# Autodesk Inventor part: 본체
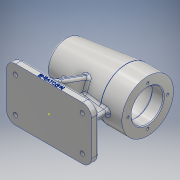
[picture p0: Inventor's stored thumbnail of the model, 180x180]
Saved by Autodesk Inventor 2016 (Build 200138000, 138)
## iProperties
Created: 2018-09
Part Number: 본체
Material: 알루미늄 6061
Document SubType Name: Modeling
Designer: CAMTIC
Density: 2.7 g/cm^3
Appearance: 알루미늄 - 평지
Mass: 734.322 g
Surface Area: 664.891 cm^2
Volume: 271.971 cm^3
Author: CAMTIC
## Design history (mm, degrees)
sketch "스케치1"
  geometry: L1 (56, -35)-(-56, -35); L2 (-56, -35)-(-56, 35); L3 (-56, 35)-(56, 35); L4 (56, 35)-(56, -35); L5 (0, -49)-(0, 49) reference; L6 (-78.4, 0)-(78.4, 0) reference; 1 further point
  constraints: 8 end point, 2 parallel, 1 horizontal, 1 perpendicular, 2 other
  dimensions: "d0" = 112 distance of L2.end L3.end; "d1" = 70 distance of L1.end L2.end
extrude "돌출1" new body sketch "스케치1" distance "d2" = 10; taper "d3" = 0 deg
sketch "스케치3"
  geometry: L1 (-56, 0)-(-56, 10) reference; L2 (-56, 10)-(56, 10) reference; L3 (56, 10)-(56, 0) reference; L4 (56, 0)-(-56, 0) reference; L5 (-78.4, 0)-(78.4, 0) reference; L6 (0, 12)-(0, -2) reference; L7 (-89.894, 74)-(120.731, 74); L8 (56, 74)-(56, 108); L9 (56, 108)-(28, 108); L10 (-56, 115.931)-(-56, 37.674); L11 (28, 108)-(-52.27, 98.144); L12 (-56, 74)-(56, 74); A1 r 80 centre (24, 74) between (54.397, 0) and (56, 0.679); A2 r 80 centre (24, 74) between (-52.27, 98.144) and (-56, 74); 1 further point
  constraints: 12 end point, 5 point on line, 4 point on circle, 2 centre point, 2 collinear, 2 horizontal, 2 vertical, 1 tangent
  dimensions: "d4" = 74 distance between parallel lines of L7 L4; "d5" = 34 distance of L8.start L8.end; "d6" = 28 distance of L8.end L9.end; "d7" = 112 distance between parallel lines of L8 L10; "d8" = 7 deg angle of L9 L11; "d10" = 80 radius of A2
revolve "회전1" sketch "스케치3" stored, may be unused: angle "d11" = 90 deg
sketch "스케치4"
  geometry: L1 (-56, 0)-(-56, 10) reference; L2 (-56, 10)-(56, 10) reference; L3 (56, 10)-(56, 0) reference; L4 (56, 0)-(-56, 0) reference; L5 (-52.27, 98.144)-(28, 108) reference; L6 (28, 108)-(56, 108) reference; L7 (56, 108)-(56, 40) reference; L8 (56, 40)-(28, 40) reference; L9 (28, 40)-(-52.27, 49.856) reference; L10 (-38, 10)-(-25.942, 55); L11 (-25.942, 55)-(38, 55); L12 (38, 55)-(38, 10); L13 (56, 10)-(-56, 10) reference; L14 (38, 10)-(-38, 10); A1 r 80 centre (24, 74) between (-52.27, 98.144) and (-52.27, 49.856) reference; 1 further point
  constraints: 8 end point, 2 point on line, 1 collinear, 1 horizontal, 1 perpendicular
  dimensions: "d12" = 18 distance from line of L1 L10.start; "d13" = 18 distance between parallel lines of L3 L12; "d14" = 105 deg angle of L2 L10; "d15" = 45 distance of L11.end L12.end
extrude "돌출2" join sketch "스케치4" stored distance "d16" = 8; taper "d17" = 0 deg
fillet "모깎기2" dims "d51" = 12
fillet "모깎기13" dims "d75" = 3
sketch "스케치5"
  geometry: L1 (7, -35)-(0, -35) reference; L2 (0, -35)-(0, 35) reference; L3 (0, 35)-(7, 35) reference; L4 (10, 32)-(10, 4) reference; L5 (10, 4)-(43.701, 4) reference; L6 (43.701, -4)-(10, -4) reference; L7 (10, -4)-(10, -32) reference; L8 (0, 49)-(0, -49) reference; L9 (-21.6, 0)-(129.6, 0) reference; L10 (10, -35)-(10, 35) reference; L11 (10, 35)-(10, -35); L12 (60, -15.902)-(60, 15.902); L13 (60, 15.902)-(8.026, 34.819); L14 (60, -15.902)-(8.026, -34.819); L15 (8.026, 34.819)-(8.026, -34.819); A1 r 30.562 centre (74, 0) between (43.701, -4) and (43.701, 4) reference; A2 r 3 centre (7, -32) between (7, -35) and (10, -32) reference; A3 r 3 centre (7, 32) between (10, 32) and (7, 35) reference; 1 further point
  constraints: 10 end point, 2 symmetric about line, 1 parallel, 1 point on circle, 1 point on line, 1 tangent, 1 vertical
  dimensions: "d19" = 50 distance between parallel lines of L7 L12; "d76" = 20 deg angle of L13 L3
extrude "돌출3" join sketch "스케치5" stored distance "d20" = 8; taper "d21" = 0 deg
sketch "스케치6"
  geometry: L1 (56, 7)-(56, 0) reference; L2 (56, 0)-(-56, 0) reference; L3 (-56, 0)-(-56, 7) reference; L4 (-53, 10)-(-38, 10) reference; L5 (-38, 10)-(-28.115, 46.89) reference; L6 (-28.115, 46.89)-(-52.27, 49.856) reference; L7 (-52.27, 98.144)-(28, 108) reference; L8 (28, 108)-(56, 108) reference; L9 (56, 108)-(56, 40) reference; L10 (56, 40)-(38, 40) reference; L11 (38, 40)-(38, 10) reference; L12 (38, 10)-(53, 10) reference; L13 (-78.4, 0)-(78.4, 0) reference; L14 (0, 129.6)-(0, -21.6) reference; L15 (56, 40)-(56, 108) reference; L16 (56, 95)-(41, 95); L17 (41, 95)-(41, 98); L18 (41, 98)-(-13, 98); L19 (-13, 98)-(-13, 95); L20 (-13, 95)-(-25, 95); L21 (-25, 95)-(-25, 91.5); L22 (-25, 91.5)-(-43, 91.5); L23 (-43, 91.5)-(-43, 90); L24 (-43, 90)-(-47, 90); L25 (-47, 90)-(-47, 84.5); L26 (-52.27, 49.856)-(-52.27, 98.144) reference; L27 (-47, 84.5)-(-50, 84.5); L28 (-50, 84.5)-(-50, 74); L29 (56, 74)-(-128.462, 74); L30 (-50, 74)-(56, 74); L31 (56, 95)-(56, 74); A1 r 80 centre (24, 74) between (-52.27, 98.144) and (-52.27, 49.856) reference; A2 r 3 centre (53, 7) between (56, 7) and (53, 10) reference; A3 r 3 centre (-53, 7) between (-53, 10) and (-56, 7) reference; 1 further point
  constraints: 30 end point, 12 perpendicular, 2 collinear, 2 point on line, 1 midpoint, 1 parallel
  dimensions: "d22" = 21 distance between parallel lines of L29 L16; "d23" = 15 distance of L16.start L16.end; "d24" = 54 distance of L17.end L18.end; "d25" = 24 distance between parallel lines of L29 L18; "d26" = 12 distance of L19.end L20.end; "d27" = 21 distance between parallel lines of L29 L20; "d28" = 18 distance of L21.end L22.end; "d29" = 17.5 distance between parallel lines of L29 L22; "d30" = 4 distance of L23.end L24.end; "d31" = 16 distance between parallel lines of L29 L24; "d32" = 10.5 distance between parallel lines of L29 L27; "d33" = 3 distance of L25.end L27.end
revolve "회전2" sketch "스케치6" stored, may be unused: angle "d34" = 90 deg
fillet "모깎기1" dims "d38" = 3, "d39" = 0.3
chamfer "모따기1" distance "d35" = 1; stored, may be unused: second distance "d36" = 2, angle "d37" = 45 deg
sketch "스케치7" dims "d40" = 52
  geometry: L1 (0, 0)-(0, 55.004); C1 r 10.5 at (0, 0) reference; 3 further points
  constraints: 2 end point, 1 coincident, 1 point on line, 1 vertical, 1 vertical alignment, 2 other
hole "구멍1" sketch "스케치7" at (0, 26) diameter "d41" = 3.242; stored, may be unused: countersink angle "d45" = 90 deg, drill point angle "d47" = 118 deg; dims "d42" = 8, "d43" = 4, "d44" = 2, "d46" = 11
hole "구멍2" diameter "d54" = 5.5; stored, may be unused: countersink angle "d58" = 90 deg, drill point angle "d60" = 118 deg; dims "d52" = 10, "d53" = 10, "d55" = 8, "d56" = 9.5, "d57" = 5.4, "d59" = 11
fillet "모깎기12" dims "d74" = 3
fillet "모깎기14" dims "d77" = 3
fillet "모깎기15" dims "d78" = 3
sketch "스케치9"
  geometry: L1 (88, 0)-(0, 0) reference; L2 (100, 0)-(100, 7) reference; 2 further points
  constraints: 1 other
  dimensions: "d84" = 3 distance from line of L1 point (44, 3); "d85" = 56 distance from line of L2 point (44, 3)
feature "엠보싱2" sketch "스케치9" dims "d0" = 112, "d1" = 70, "d86" = 0.5, "d87" = 0
fillet "모깎기17" dims "d88" = 3
fillet "모깎기18" dims "d89" = 3
fillet "모깎기19" dims "d90" = 3
fillet "모깎기20" dims "d91" = 3
fillet "모깎기21" dims "d92" = 3
node "솔리드1"
pattern_circular "원형 패턴1" dims angle "d49" = 360 deg
mirror "대칭1"
mirror "대칭2"
node "절단 모서리 투영1"
node "절단 모서리 투영2"
node "절단 모서리 투영3"
node "절단 모서리 투영4"
